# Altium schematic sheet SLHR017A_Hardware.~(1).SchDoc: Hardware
size 431 x 279 mm; Date: Not shown in title block; ApprovedBy: Not shown in title block; CheckedBy: Not shown in title block; Author: Not shown in title block; CompanyName: Not shown in title block; DrawnBy: Kirby Kruckmeyer; Engineer: Not shown in title block; Organization: Not shown in title block; Address1: Not shown in title block; Address2: Not shown in title block; Address3: Not shown in title block; Address4: Not shown in title block; DocumentNumber: 2; Revision: Use project parameter SCH_Rev; SheetNumber: 2; SheetTotal: 2; PageSetup: Record=PageOptions¦CenterHorizontal=True¦CenterVertical=True¦PrintScale=1.00¦XCorrection=1.00¦YCorrection=1.00¦PrintKind=0¦BorderSize=5000000¦LeftOffset=0¦BottomOffset=0¦Orientation=2¦PaperLength=1000¦PaperWidth=1000¦Scale=100¦PaperSource=15¦PrintQuality=600¦MediaType=1¦DitherType=10¦PaperKind=Letter¦PrintScaleMode=1
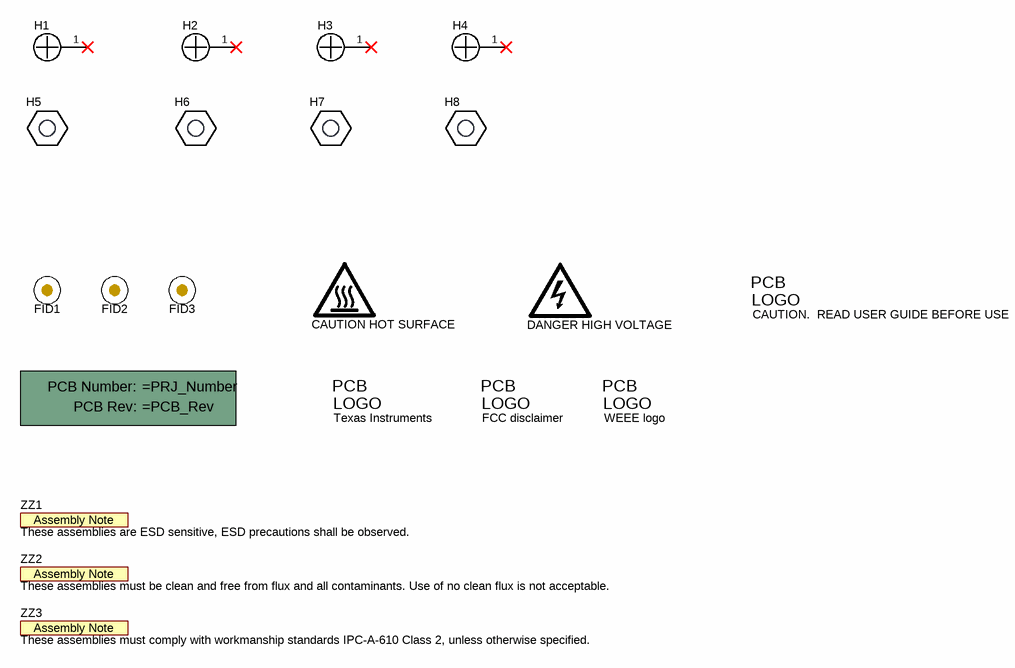
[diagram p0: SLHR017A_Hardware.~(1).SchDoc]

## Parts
!PCB1  Printed Circuit Board  (value not drawn)  (mechanical)
FID1  Fiducial  [Fiducial10-20]  (value not drawn)
FID2  Fiducial  [Fiducial10-20]  (value not drawn)
FID3  Fiducial  [Fiducial10-20]  (value not drawn)
H1  NY PMS 440 0025 PH  [NY PMS 440 0025 PH]  (value not drawn)
H2  NY PMS 440 0025 PH  [NY PMS 440 0025 PH]  (value not drawn)
H3  NY PMS 440 0025 PH  [NY PMS 440 0025 PH]  (value not drawn)
H4  NY PMS 440 0025 PH  [NY PMS 440 0025 PH]  (value not drawn)
H5  1902C  [Keystone_1902C]  (value not drawn)
H6  1902C  [Keystone_1902C]  (value not drawn)
H7  1902C  [Keystone_1902C]  (value not drawn)
H8  1902C  [Keystone_1902C]  (value not drawn)
LOGO1  DANGER HIGH VOLTAGE  [IEC_HighVoltage_Small]  (no BOM)
LOGO2  CAUTION HOT SURFACE  [IEC_HotSurface_Small]  (no BOM)
Logo3  CAUTION.  READ USER GUIDE BEFORE USE  [IEC_Caution_Small]  (no BOM)
Logo5  Texas Instruments  [TI_Stacked_Overlay_Small]  (no BOM)
Logo6  FCC disclaimer  [FCC_disclaimer]  (no BOM)
Logo7  WEEE logo  [WEEE_Minimum]  (no BOM)
ZZ1  These assemblies are ESD sensitive, ESD precautions shall be observed.  [AssemblyNote]  (no BOM)
ZZ2  These assemblies must be clean and free from flux and all contaminants. Use of no clean flux is not acceptable.  [AssemblyNote]  (no BOM)
ZZ3  These assemblies must comply with workmanship standards IPC-A-610 Class 2, unless otherwise specified.  [AssemblyNote]  (no BOM)

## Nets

Not connected (* = marked no-connect by the designer): H1 1*; H2 1*; H3 1*; H4 1*

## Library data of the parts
!PCB1 = CMP-0003618-2: Manufacturer: Any
FID1-FID3 = CMP-0077181-1: Fiducial mark.  There is nothing to buy or mount.
H1-H4 = CMP-0003617-1: Machine Screw, Round, #4-40 x 1/4, Nylon, Philips panhead; Manufacturer: B&F Fastener Supply; CompType: Hardware
H5-H8 = CMP-0003610-1: Standoff, Hex, 0.5"L #4-40 Nylon; Manufacturer: Keystone; CompType: Hardware
LOGO1 = CMP-0074835-1: IEC 61010-1 High Voltage Warning; SymbolCreator: a0412235; Lib Reference: IEC_HighVoltage
LOGO2 = CMP-0074837-1: IEC 61010-1 Hot Surface Warning; SymbolCreator: a0412235; Lib Reference: IEC_HotSurface
Logo3 = CMP-0074836-1: IEC 61010-1 Caution Warning; SymbolCreator: a0412235; Lib Reference: IEC_Caution; Library Reference: Logo
Logo5 = CMP-0074838-1: Texas Instrument Corporate Signature; SymbolCreator: a0412235; Lib Reference: TI_Logo; Library Reference: Logo
Logo6 = CMP-0074847-1: FCC_disclaimer; Library Reference: Logo
Logo7 = CMP-0074769-1
ZZ1 = CMP-0077236-1
ZZ2 = CMP-0077237-1
ZZ3 = CMP-0077238-1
